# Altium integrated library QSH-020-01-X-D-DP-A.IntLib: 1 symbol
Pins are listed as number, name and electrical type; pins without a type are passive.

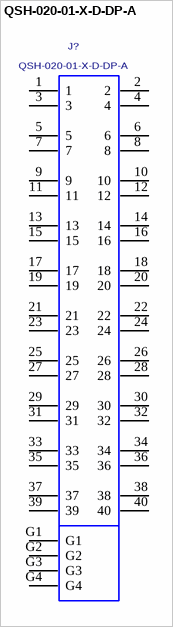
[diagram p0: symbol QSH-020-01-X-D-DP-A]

## QSH-020-01-X-D-DP-A
designator J?
HIGH SPEED SOCKET, 0.5mm PITCH, DIFFERENTIAL PAIRS, 40 PINS.; MANUFACTURER: SAMTEC, INC
footprint QSH-020-01-X-D-DP-A
pins: 1, 2, 3, 4, 5, 6, 7, 8, 9, 10, 11, 12, 13, 14, 15, 16, 17, 18, 19, 20, 21, 22, 23, 24, 25, 26, 27, 28, 29, 30, 31, 32, 33, 34, 35, 36, 37, 38, 39, 40, G1, G2, G3, G4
